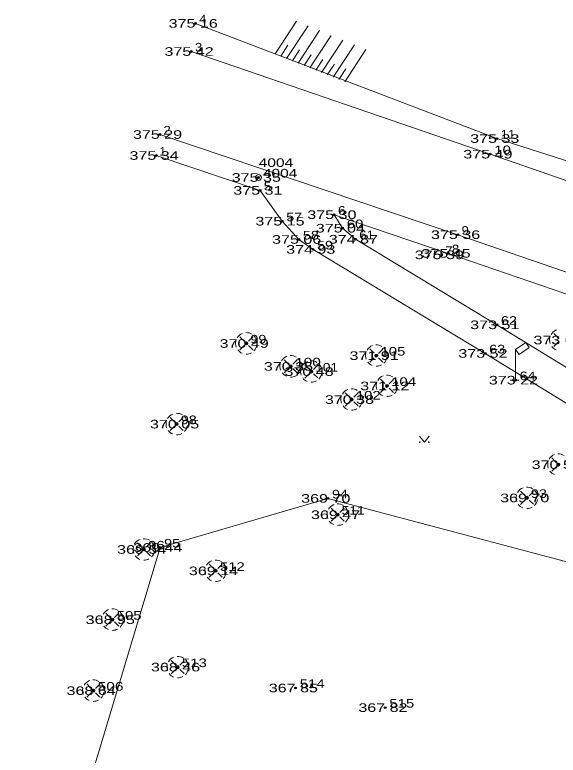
# Model space of a CAD drawing. Extents: x -789669 to -789458, y -977587 to -977420.
# Drawn here: x -789666.7 to -789622.4, y -977479.9 to -977419.6 of the extents above; entities that cross this region are included whole.
import ezdxf
from ezdxf.enums import TextEntityAlignment as Align

# ---------------------------------------------------------------- set-up
doc = ezdxf.new("R2010")
doc.units = 0
doc.header["$LTSCALE"] = 0.28
doc.header["$PDMODE"] = 32
doc.header["$PDSIZE"] = 0.14
for name, color, linetype, lineweight in [('1', 7, 'Continuous', 13), ('2', 7, 'Continuous', 13), ('3', 7, 'Continuous', 13), ('33', 7, 'Continuous', 13), ('4', 7, 'Continuous', 13), ('50', 7, 'Continuous', 13)]:
    doc.layers.add(name, color=color, linetype=linetype, lineweight=lineweight)
for name, color, linetype in [('57', 7, 'Continuous'), ('58', 7, 'Continuous'), ('59', 7, 'Continuous')]:
    doc.layers.add(name, color=color, linetype=linetype)

msp = doc.modelspace()

# ---------------------------------------------------------------- linework, layer by layer
at = {"layer": '1'}
for points in [[(-789652.33, -977422.61), (-789627.98, -977430.97), (-789609.02, -977437.54), (-789583.63, -977446.35), (-789563.97, -977453.25), (-789542.04, -977460.63), (-789524.21, -977466.84), (-789507.23, -977472.64), (-789487.17, -977479.36)], [(-789509.64, -977479.12), (-789526.32, -977473.4), (-789544.78, -977467.07), (-789566.2, -977459.68), (-789586.28, -977452.77), (-789604.78, -977446.41), (-789630.61, -977437.53), (-789654.9, -977429.37)], [(-789655.18, -977431.08), (-789646.72, -977433.92), (-789644.92, -977436.43), (-789643.56, -977437.92), (-789642.41, -977438.73)], [(-789638.94, -977437.9), (-789640, -977437), (-789640.69, -977435.9), (-789631.39, -977439.05), (-789605.73, -977447.87), (-789604.26, -977448.38)], [(-789638.94, -977437.9), (-789627.42, -977444.87), (-789610.68, -977455.13), (-789609.37, -977455.85), (-789603.31, -977459.5)], [(-789605.23, -977462.77), (-789609.01, -977460.5), (-789610.31, -977459.07), (-789610.84, -977457.94), (-789611.05, -977457.83), (-789612.47, -977456.96), (-789628.38, -977447.2), (-789642.41, -977438.73)]]:
    msp.add_lwpolyline(points, dxfattribs=at)
at = {"layer": '2'}
for p, q in [((-789643.762, -977420.144), (-789645.503, -977422.797)), ((-789644.558, -977423.179), (-789642.817, -977420.527)), ((-789643.612, -977423.561), (-789641.873, -977420.911)), ((-789642.667, -977423.943), (-789640.928, -977421.294)), ((-789645.03, -977422.988), (-789644.45, -977422.104)), ((-789641.722, -977424.325), (-789639.984, -977421.677)), ((-789640.776, -977424.707), (-789639.039, -977422.061)), ((-789644.085, -977423.37), (-789643.505, -977422.486)), ((-789639.831, -977425.09), (-789638.095, -977422.444)), ((-789643.14, -977423.752), (-789642.56, -977422.869)), ((-789642.194, -977424.134), (-789641.615, -977423.251)), ((-789641.249, -977424.516), (-789640.67, -977423.634)), ((-789640.304, -977424.898), (-789639.725, -977424.016))]:
    msp.add_line(p, q, dxfattribs=at)
msp.add_lwpolyline([(-789651.99, -977420.32), (-789627.42, -977429.7), (-789608.58, -977435.72), (-789582.71, -977444.73), (-789563.37, -977451.38), (-789541.29, -977458.45), (-789523.64, -977464.38), (-789506.63, -977471.11), (-789487.17, -977479.36)], dxfattribs=at)
at = {"layer": '3'}
msp.add_lwpolyline([(-789666.71, -977502.39), (-789654.87, -977463.01), (-789641.19, -977459.01), (-789614.78, -977466.03), (-789608.83, -977467.57), (-789606.74, -977465.22)], dxfattribs=at)
at = {"layer": '33'}
for p, q in [((-789625.9, -977446.88), (-789625.9, -977449.38)), ((-789626.15, -977449.38), (-789625.65, -977449.38))]:
    msp.add_line(p, q, dxfattribs=at)
msp.add_lwpolyline([(-789625.9, -977446.88), (-789625.08, -977446.307), (-789624.794, -977446.717), (-789625.614, -977447.29)], close=True, dxfattribs=at)
at = {"layer": '4'}
for p, q in [((-789622.794, -977445.566), (-789622.437, -977445.922)), ((-789648.374, -977445.846), (-789648.017, -977446.202)), ((-789647.314, -977445.854), (-789647.667, -977446.207)), ((-789622.79, -977446.637), (-789622.438, -977446.286)), ((-789648.37, -977446.917), (-789648.018, -977446.566)), ((-789647.84, -977446.39), (-789647.84, -977446.378)), ((-789647.666, -977446.561), (-789647.314, -977446.911)), ((-789637.784, -977446.836), (-789637.427, -977447.192)), ((-789636.724, -977446.844), (-789637.077, -977447.197)), ((-789637.78, -977447.907), (-789637.428, -977447.556)), ((-789637.25, -977447.38), (-789637.25, -977447.368)), ((-789637.076, -977447.551), (-789636.724, -977447.901)), ((-789644.764, -977447.716), (-789644.407, -977448.072)), ((-789643.704, -977447.724), (-789644.057, -977448.077)), ((-789643.084, -977448.136), (-789642.727, -977448.492)), ((-789642.024, -977448.144), (-789642.377, -977448.497)), ((-789644.76, -977448.787), (-789644.408, -977448.436)), ((-789644.23, -977448.26), (-789644.23, -977448.248)), ((-789644.056, -977448.431), (-789643.704, -977448.781)), ((-789642.55, -977448.68), (-789642.55, -977448.668)), ((-789643.08, -977449.207), (-789642.728, -977448.856)), ((-789642.376, -977448.851), (-789642.024, -977449.201)), ((-789636.914, -977449.306), (-789636.557, -977449.662)), ((-789635.854, -977449.314), (-789636.207, -977449.667)), ((-789636.38, -977449.85), (-789636.38, -977449.838)), ((-789639.794, -977450.416), (-789639.437, -977450.772)), ((-789638.734, -977450.424), (-789639.087, -977450.777)), ((-789636.91, -977450.377), (-789636.558, -977450.026)), ((-789636.206, -977450.021), (-789635.854, -977450.371)), ((-789639.79, -977451.487), (-789639.438, -977451.136)), ((-789639.26, -977450.96), (-789639.26, -977450.948)), ((-789639.086, -977451.131), (-789638.734, -977451.481)), ((-789654.044, -977452.416), (-789653.687, -977452.772)), ((-789653.51, -977452.96), (-789653.51, -977452.948)), ((-789652.984, -977452.424), (-789653.337, -977452.777)), ((-789654.04, -977453.487), (-789653.688, -977453.136)), ((-789653.336, -977453.131), (-789652.984, -977453.481)), ((-789622.944, -977455.716), (-789622.587, -977456.072)), ((-789622.94, -977456.787), (-789622.588, -977456.436)), ((-789625.514, -977458.426), (-789625.157, -977458.782)), ((-789624.98, -977458.97), (-789624.98, -977458.958)), ((-789624.454, -977458.434), (-789624.807, -977458.787)), ((-789625.51, -977459.497), (-789625.158, -977459.146)), ((-789624.806, -977459.141), (-789624.454, -977459.491)), ((-789640.924, -977459.796), (-789640.567, -977460.152)), ((-789639.864, -977459.804), (-789640.217, -977460.157)), ((-789640.92, -977460.867), (-789640.568, -977460.516)), ((-789640.39, -977460.34), (-789640.39, -977460.328)), ((-789640.216, -977460.511), (-789639.864, -977460.861)), ((-789656.724, -977462.626), (-789656.367, -977462.982)), ((-789655.664, -977462.634), (-789656.017, -977462.987)), ((-789656.19, -977463.17), (-789656.19, -977463.158)), ((-789656.72, -977463.697), (-789656.368, -977463.346)), ((-789656.016, -977463.341), (-789655.664, -977463.691)), ((-789650.874, -977464.366), (-789650.517, -977464.722)), ((-789649.814, -977464.374), (-789650.167, -977464.727)), ((-789650.34, -977464.91), (-789650.34, -977464.898)), ((-789650.87, -977465.437), (-789650.518, -977465.086)), ((-789650.166, -977465.081), (-789649.814, -977465.431)), ((-789659.284, -977468.346), (-789658.927, -977468.702)), ((-789658.224, -977468.354), (-789658.577, -977468.707)), ((-789659.28, -977469.417), (-789658.928, -977469.066)), ((-789658.75, -977468.89), (-789658.75, -977468.878)), ((-789658.576, -977469.061), (-789658.224, -977469.411)), ((-789653.964, -977472.218), (-789653.607, -977472.574)), ((-789652.904, -977472.226), (-789653.257, -977472.579)), ((-789653.43, -977472.762), (-789653.43, -977472.75)), ((-789653.96, -977473.289), (-789653.608, -977472.938)), ((-789653.256, -977472.933), (-789652.904, -977473.283)), ((-789660.844, -977474.126), (-789660.487, -977474.482)), ((-789660.31, -977474.67), (-789660.31, -977474.658)), ((-789659.784, -977474.134), (-789660.137, -977474.487)), ((-789660.84, -977475.197), (-789660.488, -977474.846)), ((-789660.136, -977474.841), (-789659.784, -977475.191))]:
    msp.add_line(p, q, dxfattribs=at)
for points in [[(-789633.74, -977453.952), (-789633.338, -977454.431), (-789632.936, -977453.952)], [(-789633.712, -977454.408), (-789633.698, -977454.416), (-789633.693, -977454.431), (-789633.699, -977454.444), (-789633.712, -977454.452), (-789633.728, -977454.444), (-789633.734, -977454.431), (-789633.73, -977454.417), (-789633.719, -977454.411), (-789633.704, -977454.417), (-789633.699, -977454.431), (-789633.702, -977454.441), (-789633.712, -977454.446), (-789633.723, -977454.441), (-789633.729, -977454.43), (-789633.724, -977454.42), (-789633.719, -977454.417), (-789633.708, -977454.421), (-789633.703, -977454.431), (-789633.709, -977454.438), (-789633.717, -977454.436), (-789633.722, -977454.428), (-789633.717, -977454.423), (-789633.709, -977454.427), (-789633.712, -977454.431)], [(-789632.962, -977454.409), (-789632.948, -977454.417), (-789632.943, -977454.432), (-789632.949, -977454.445), (-789632.962, -977454.453), (-789632.978, -977454.445), (-789632.984, -977454.432), (-789632.98, -977454.418), (-789632.969, -977454.412), (-789632.954, -977454.418), (-789632.949, -977454.432), (-789632.952, -977454.442), (-789632.962, -977454.447), (-789632.973, -977454.442), (-789632.979, -977454.431), (-789632.974, -977454.421), (-789632.969, -977454.418), (-789632.958, -977454.422), (-789632.953, -977454.432), (-789632.959, -977454.439), (-789632.967, -977454.437), (-789632.972, -977454.429), (-789632.967, -977454.424), (-789632.959, -977454.428), (-789632.962, -977454.432)]]:
    msp.add_lwpolyline(points, dxfattribs=at)
for centre, radius in [((-789647.8439, -977446.3834), 0.125), ((-789637.2539, -977447.3734), 0.125), ((-789644.2339, -977448.2534), 0.125), ((-789642.5539, -977448.6734), 0.125), ((-789636.3839, -977449.8434), 0.125), ((-789639.2639, -977450.9534), 0.125), ((-789653.5139, -977452.9534), 0.125), ((-789633.713, -977454.431), 0.025), ((-789632.963, -977454.431), 0.025), ((-789622.4139, -977456.2534), 0.125), ((-789624.9839, -977458.9634), 0.125), ((-789640.3939, -977460.3334), 0.125), ((-789656.1939, -977463.1634), 0.125), ((-789650.3439, -977464.9034), 0.125), ((-789658.7539, -977468.8834), 0.125), ((-789653.4339, -977472.7554), 0.125), ((-789660.3139, -977474.6634), 0.125)]:
    msp.add_circle(centre, radius, dxfattribs=at)
for centre, start, end in [((-789647.8439, -977446.3834), 111.04924, 149.34666), ((-789647.8439, -977446.3834), 57.94289, 92.85253), ((-789622.2639, -977446.1034), 111.04924, 149.34666), ((-789647.8439, -977446.3834), 166.76695, 200.11735), ((-789647.8439, -977446.3834), 9.68453, 44.47714), ((-789622.2639, -977446.1034), 166.76695, 200.11735), ((-789647.8439, -977446.3834), 217.06959, 247.69959), ((-789647.8439, -977446.3834), 315.09105, 351.67435), ((-789637.2539, -977447.3734), 111.04924, 149.34666), ((-789637.2539, -977447.3734), 57.94289, 92.85253), ((-789637.2539, -977447.3734), 9.68453, 44.47714), ((-789622.2639, -977446.1034), 217.06959, 247.69959), ((-789647.8439, -977446.3834), 269.18965, 298.56841), ((-789644.2339, -977448.2534), 111.04924, 149.34666), ((-789644.2339, -977448.2534), 57.94289, 92.85253), ((-789637.2539, -977447.3734), 166.76695, 200.11735), ((-789637.2539, -977447.3734), 315.09105, 351.67435), ((-789644.2339, -977448.2534), 166.76695, 200.11735), ((-789644.2339, -977448.2534), 9.68453, 44.47714), ((-789642.5539, -977448.6734), 111.04924, 149.34666), ((-789642.5539, -977448.6734), 57.94289, 92.85253), ((-789642.5539, -977448.6734), 9.68453, 44.47714), ((-789637.2539, -977447.3734), 217.06959, 247.69959), ((-789637.2539, -977447.3734), 269.18965, 298.56841), ((-789644.2339, -977448.2534), 315.09105, 351.67435), ((-789642.5539, -977448.6734), 166.76695, 200.11735), ((-789644.2339, -977448.2534), 217.06959, 247.69959), ((-789644.2339, -977448.2534), 269.18965, 298.56841), ((-789642.5539, -977448.6734), 217.06959, 247.69959), ((-789642.5539, -977448.6734), 315.09105, 351.67435), ((-789636.3839, -977449.8434), 111.04924, 149.34666), ((-789636.3839, -977449.8434), 57.94289, 92.85253), ((-789636.3839, -977449.8434), 9.68453, 44.47714), ((-789642.5539, -977448.6734), 269.18965, 298.56841), ((-789636.3839, -977449.8434), 166.76695, 200.11735), ((-789636.3839, -977449.8434), 315.09105, 351.67435), ((-789639.2639, -977450.9534), 111.04924, 149.34666), ((-789639.2639, -977450.9534), 57.94289, 92.85253), ((-789639.2639, -977450.9534), 9.68453, 44.47714), ((-789636.3839, -977449.8434), 217.06959, 247.69959), ((-789639.2639, -977450.9534), 166.76695, 200.11735), ((-789639.2639, -977450.9534), 315.09105, 351.67435), ((-789636.3839, -977449.8434), 269.18965, 298.56841), ((-789639.2639, -977450.9534), 217.06959, 247.69959), ((-789639.2639, -977450.9534), 269.18965, 298.56841), ((-789653.5139, -977452.9534), 111.04924, 149.34666), ((-789653.5139, -977452.9534), 57.94289, 92.85253), ((-789653.5139, -977452.9534), 9.68453, 44.47714), ((-789653.5139, -977452.9534), 166.76695, 200.11735), ((-789653.5139, -977452.9534), 217.06959, 247.69959), ((-789653.5139, -977452.9534), 315.09105, 351.67435), ((-789653.5139, -977452.9534), 269.18965, 298.56841), ((-789622.4139, -977456.2534), 57.94289, 92.85253), ((-789622.4139, -977456.2534), 111.04924, 149.34666), ((-789622.4139, -977456.2534), 166.76695, 200.11735), ((-789622.4139, -977456.2534), 217.06959, 247.69959), ((-789624.9839, -977458.9634), 111.04924, 149.34666), ((-789624.9839, -977458.9634), 57.94289, 92.85253), ((-789624.9839, -977458.9634), 9.68453, 44.47714), ((-789624.9839, -977458.9634), 166.76695, 200.11735), ((-789640.3939, -977460.3334), 111.04924, 149.34666), ((-789640.3939, -977460.3334), 57.94289, 92.85253), ((-789624.9839, -977458.9634), 217.06959, 247.69959), ((-789624.9839, -977458.9634), 315.09105, 351.67435), ((-789640.3939, -977460.3334), 166.76695, 200.11735), ((-789640.3939, -977460.3334), 9.68453, 44.47714), ((-789624.9839, -977458.9634), 269.18965, 298.56841), ((-789640.3939, -977460.3334), 315.09105, 351.67435), ((-789640.3939, -977460.3334), 217.06959, 247.69959), ((-789640.3939, -977460.3334), 269.18965, 298.56841), ((-789656.1939, -977463.1634), 111.04924, 149.34666), ((-789656.1939, -977463.1634), 57.94289, 92.85253), ((-789656.1939, -977463.1634), 9.68453, 44.47714), ((-789656.1939, -977463.1634), 166.76695, 200.11735), ((-789656.1939, -977463.1634), 217.06959, 247.69959), ((-789656.1939, -977463.1634), 315.09105, 351.67435), ((-789656.1939, -977463.1634), 269.18965, 298.56841), ((-789650.3439, -977464.9034), 111.04924, 149.34666), ((-789650.3439, -977464.9034), 57.94289, 92.85253), ((-789650.3439, -977464.9034), 9.68453, 44.47714), ((-789650.3439, -977464.9034), 166.76695, 200.11735), ((-789650.3439, -977464.9034), 315.09105, 351.67435), ((-789650.3439, -977464.9034), 217.06959, 247.69959), ((-789650.3439, -977464.9034), 269.18965, 298.56841), ((-789658.7539, -977468.8834), 57.94289, 92.85253), ((-789658.7539, -977468.8834), 111.04924, 149.34666), ((-789658.7539, -977468.8834), 9.68453, 44.47714), ((-789658.7539, -977468.8834), 166.76695, 200.11735), ((-789658.7539, -977468.8834), 315.09105, 351.67435), ((-789658.7539, -977468.8834), 217.06959, 247.69959), ((-789658.7539, -977468.8834), 269.18965, 298.56841), ((-789653.4339, -977472.7554), 111.04924, 149.34666), ((-789653.4339, -977472.7554), 57.94289, 92.85253), ((-789653.4339, -977472.7554), 9.68453, 44.47714), ((-789653.4339, -977472.7554), 166.76695, 200.11735), ((-789653.4339, -977472.7554), 315.09105, 351.67435), ((-789653.4339, -977472.7554), 217.06959, 247.69959), ((-789660.3139, -977474.6634), 111.04924, 149.34666), ((-789660.3139, -977474.6634), 57.94289, 92.85253), ((-789660.3139, -977474.6634), 9.68453, 44.47714), ((-789653.4339, -977472.7554), 269.18965, 298.56841), ((-789660.3139, -977474.6634), 166.76695, 200.11735), ((-789660.3139, -977474.6634), 217.06959, 247.69959), ((-789660.3139, -977474.6634), 315.09105, 351.67435), ((-789660.3139, -977474.6634), 269.18965, 298.56841)]:
    msp.add_arc(centre, 0.875, start, end, dxfattribs=at)
at = {"layer": '50'}
msp.add_line((-789646.858, -977432.87), (-789646.842, -977432.87), dxfattribs=at)
msp.add_circle((-789646.8498, -977432.8705), 0.24, dxfattribs=at)
at = {"layer": '57'}
for p in [(-789651.99, -977420.32), (-789652.33, -977422.61), (-789654.9, -977429.37), (-789627.42, -977429.7), (-789655.18, -977431.08), (-789627.98, -977430.97), (-789646.85, -977432.87), (-789646.72, -977433.92), (-789640.69, -977435.9), (-789644.92, -977436.43), (-789640, -977437), (-789643.56, -977437.92), (-789638.94, -977437.9), (-789630.61, -977437.53), (-789642.41, -977438.73), (-789631.93, -977439.17), (-789631.39, -977439.05), (-789627.42, -977444.87), (-789647.84, -977446.39), (-789637.25, -977447.38), (-789628.38, -977447.2), (-789644.23, -977448.26), (-789642.55, -977448.68), (-789625.9, -977449.38), (-789636.38, -977449.85), (-789639.26, -977450.96), (-789653.51, -977452.96), (-789622.41, -977456.26), (-789641.19, -977459.01), (-789624.98, -977458.97), (-789640.39, -977460.34), (-789656.19, -977463.17), (-789654.87, -977463.01), (-789650.34, -977464.91), (-789658.75, -977468.89), (-789653.43, -977472.75), (-789660.31, -977474.67), (-789643.83, -977474.45), (-789636.53, -977476.05)]:
    msp.add_point(p, dxfattribs=at)

# ---------------------------------------------------------------- texts
at = {"layer": '50', "width": 1.35}
msp.add_text(' 4004', height=0.7, dxfattribs=at).set_placement((-789647.187, -977432.008))
at = {"layer": '58'}
for s, width, p in [(' 4', 1.15, (-789651.99, -977420.32)), (' 3', 1.15, (-789652.33, -977422.61)), (' 2', 1.15, (-789654.9, -977429.37)), (' 11', 1.15, (-789627.42, -977429.7)), (' 10', 1.3, (-789627.98, -977430.97)), (' 4004', 1.35, (-789646.85, -977432.87)), (' 5', 1.15, (-789646.72, -977433.92)), (' 6', 1.2, (-789640.69, -977435.9)), (' 57', 1.25, (-789644.92, -977436.43)), (' 60', 1.3, (-789640, -977437)), (' 58', 1.25, (-789643.56, -977437.92)), (' 61', 1.15, (-789638.94, -977437.9)), (' 9', 1.15, (-789630.61, -977437.53)), (' 59', 1.25, (-789642.41, -977438.73)), (' 7', 1.15, (-789631.93, -977439.17)), (' 8', 1.15, (-789631.39, -977439.05)), (' 62', 1.25, (-789627.42, -977444.87)), (' 99', 1.25, (-789647.84, -977446.39)), (' 105', 1.3, (-789637.25, -977447.38)), (' 63', 1.25, (-789628.38, -977447.2)), (' 100', 1.35, (-789644.23, -977448.26)), (' 101', 1.2, (-789642.55, -977448.68)), (' 64', 1.25, (-789625.9, -977449.38)), (' 104', 1.3, (-789636.38, -977449.85)), (' 102', 1.3, (-789639.26, -977450.96)), (' 98', 1.25, (-789653.51, -977452.96)), (' 94', 1.25, (-789641.19, -977459.01)), (' 93', 1.25, (-789624.98, -977458.97)), (' 511', 1.2, (-789640.39, -977460.34)), (' 96', 1.3, (-789656.19, -977463.17)), (' 95', 1.25, (-789654.87, -977463.01)), (' 512', 1.3, (-789650.34, -977464.91)), (' 505', 1.3, (-789658.75, -977468.89)), (' 513', 1.3, (-789653.43, -977472.75)), (' 506', 1.35, (-789660.31, -977474.67)), (' 514', 1.3, (-789643.83, -977474.45)), (' 515', 1.3, (-789636.53, -977476.05))]:
    msp.add_text(s, height=0.7, dxfattribs=dict(at, width=width)).set_placement(p)
msp.add_text(' 1', height=0.7, dxfattribs=at).set_placement((-789655.18, -977431.08))
at = {"layer": '59', "width": 1.4}
for s, p in [('375 16 ', (-789651.99, -977420.67)), ('375 42 ', (-789652.33, -977422.96)), ('375 29 ', (-789654.9, -977429.72)), ('375 33 ', (-789627.42, -977430.05)), ('375 49 ', (-789627.98, -977431.32)), ('375 34 ', (-789655.18, -977431.43)), ('375 35 ', (-789646.85, -977433.22)), ('375 31 ', (-789646.72, -977434.27)), ('375 15 ', (-789644.92, -977436.78)), ('375 30 ', (-789640.69, -977436.25)), ('375 04 ', (-789640, -977437.35)), ('375 36 ', (-789630.61, -977437.88)), ('375 06 ', (-789643.56, -977438.27)), ('374 87 ', (-789638.94, -977438.25)), ('374 93 ', (-789642.41, -977439.08)), ('375 39 ', (-789631.93, -977439.52)), ('375 45 ', (-789631.39, -977439.4)), ('373 51 ', (-789627.42, -977445.22)), ('373 67 ', (-789622.26, -977446.46)), ('370 49 ', (-789647.84, -977446.74)), ('373 52 ', (-789628.38, -977447.55)), ('371 91 ', (-789637.25, -977447.73)), ('370 35 ', (-789644.23, -977448.61)), ('370 48 ', (-789642.55, -977449.03)), ('373 22 ', (-789625.9, -977449.73)), ('371 12 ', (-789636.38, -977450.2)), ('370 38 ', (-789639.26, -977451.31)), ('370 05 ', (-789653.51, -977453.31)), ('370 55 ', (-789622.41, -977456.61)), ('369 70 ', (-789641.19, -977459.36)), ('369 70 ', (-789624.98, -977459.32)), ('369 47 ', (-789640.39, -977460.69)), ('369 54 ', (-789656.19, -977463.52)), ('369 44 ', (-789654.87, -977463.36)), ('369 14 ', (-789650.34, -977465.26)), ('368 95 ', (-789658.75, -977469.24)), ('368 46 ', (-789653.43, -977473.1)), ('367 85 ', (-789643.83, -977474.8)), ('368 64 ', (-789660.31, -977475.02)), ('367 82 ', (-789636.53, -977476.4))]:
    msp.add_text(s, height=0.7, dxfattribs=at).set_placement(p, align=Align.CENTER)

doc.saveas('drawing.dxf')
